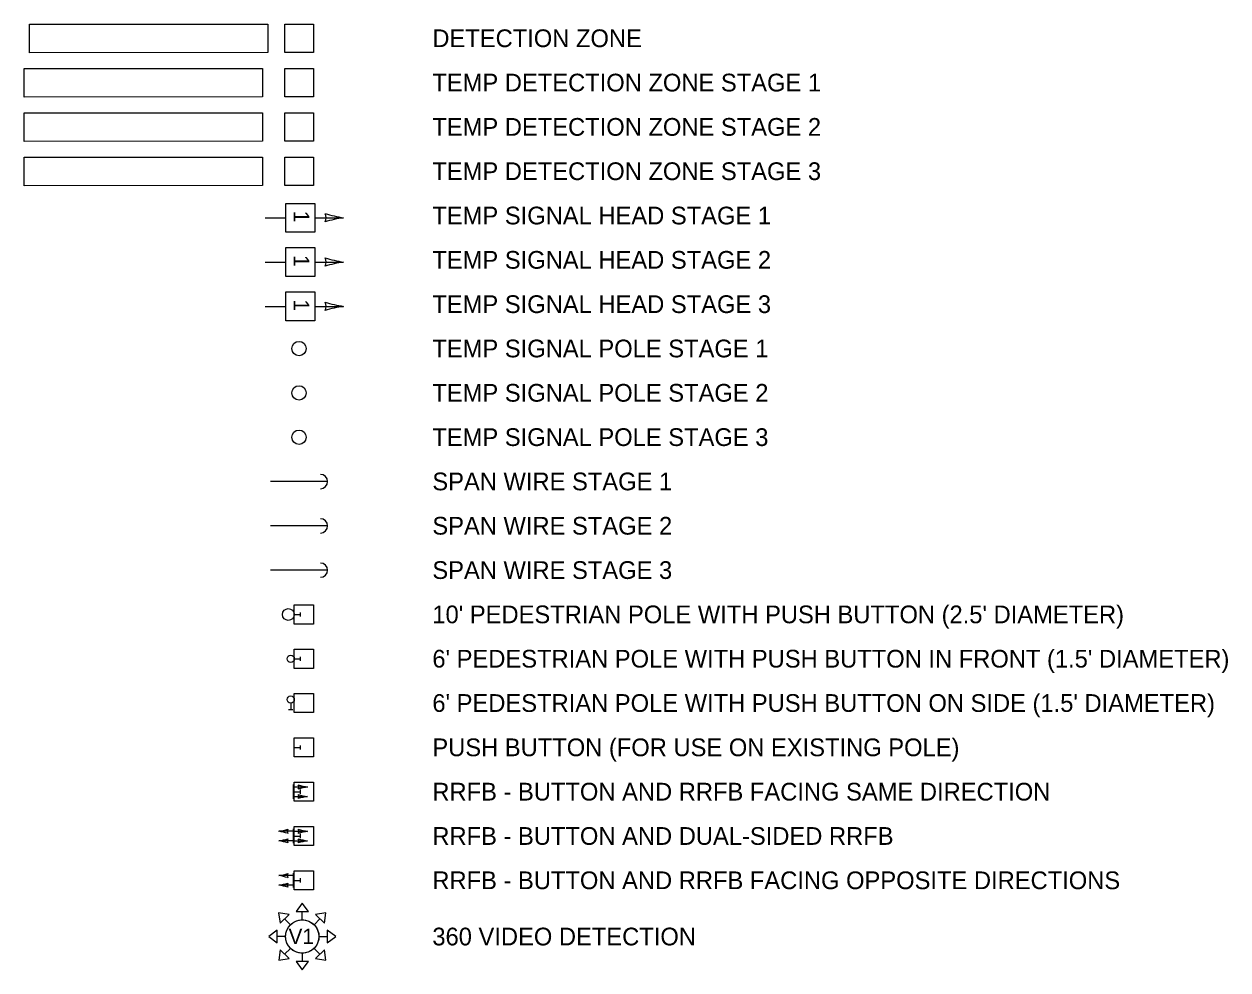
# Model space of a CAD drawing. Extents: x 993729 to 994927, y 1984823 to 1986420.
# Drawn here: x 994024.2 to 994276.7, y 1986017.7 to 1986216.2 of the extents above; entities that cross this region are included whole.
import ezdxf

# ---------------------------------------------------------------- set-up
doc = ezdxf.new("R2010")
doc.units = 0
for name, color, linetype in [('EX_BREAKLINE_PT_SYM', 7, 'Continuous'), ('EX_DROP_INLET_ANNOT', 7, 'Continuous'), ('EX_FIBER_OPTIC_CABLE', 7, 'Continuous'), ('EX_GAS_UTILITIES', 7, 'Continuous'), ('EX_LANDSCAPING', 7, 'Continuous'), ('EX_MANHOLE_ANNOT', 7, 'Continuous'), ('EX_MSC_PT_SYM', 7, 'Continuous'), ('EX_SECONDARY_CTL_ANNOT', 7, 'Continuous'), ('EX_SIGN', 7, 'Continuous'), ('EX_SIGN_ANNOT', 7, 'Continuous'), ('EX_STORM_SEWER_ANNOT', 7, 'Continuous'), ('EX_SURVEY_ANNOT', 7, 'Continuous'), ('EX_TELEPHONE_UTILITIES_ANNOT', 7, 'Continuous'), ('EX_UNDERGROUND_CABLE_ANNOT', 7, 'Continuous'), ('EX_UTILITY_MARKER', 7, 'Continuous')]:
    doc.layers.add(name, color=color, linetype=linetype)

msp = doc.modelspace()

# ---------------------------------------------------------------- linework, layer by layer
at = {"layer": 'EX_BREAKLINE_PT_SYM'}
for p, q in [((994082.59, 1986031.69), (994081.28, 1986029.93)), ((994083.9, 1986029.93), (994082.59, 1986031.69)), ((994079.81, 1986029.32), (994077.63, 1986029.63)), ((994077.63, 1986029.63), (994077.95, 1986027.46)), ((994077.95, 1986027.46), (994079.81, 1986029.32)), ((994081.28, 1986029.93), (994083.9, 1986029.93)), ((994082.59, 1986028.18), (994082.59, 1986029.93)), ((994087.55, 1986029.64), (994085.37, 1986029.32)), ((994085.37, 1986029.32), (994087.23, 1986027.46)), ((994087.23, 1986027.46), (994087.55, 1986029.64)), ((994080.12, 1986027.15), (994078.88, 1986028.39)), ((994085.07, 1986027.15), (994086.3, 1986028.39)), ((994077.34, 1986025.99), (994075.58, 1986024.68)), ((994075.58, 1986024.68), (994077.34, 1986023.37)), ((994077.34, 1986023.37), (994077.34, 1986025.99)), ((994079.09, 1986024.68), (994077.34, 1986024.68)), ((994086.09, 1986024.68), (994087.84, 1986024.68)), ((994087.84, 1986025.99), (994087.84, 1986023.37)), ((994089.6, 1986024.68), (994087.84, 1986025.99)), ((994087.84, 1986023.37), (994089.6, 1986024.68)), ((994077.95, 1986021.89), (994077.64, 1986019.72)), ((994079.81, 1986020.04), (994077.95, 1986021.89)), ((994080.12, 1986022.2), (994078.88, 1986020.97)), ((994085.07, 1986022.2), (994086.3, 1986020.97)), ((994087.23, 1986021.9), (994085.38, 1986020.04)), ((994087.55, 1986019.72), (994087.23, 1986021.9)), ((994077.64, 1986019.72), (994079.81, 1986020.04)), ((994083.9, 1986019.43), (994081.28, 1986019.43)), ((994081.28, 1986019.43), (994082.59, 1986017.67)), ((994082.59, 1986021.18), (994082.59, 1986019.43)), ((994082.59, 1986017.67), (994083.9, 1986019.43)), ((994085.38, 1986020.04), (994087.55, 1986019.72))]:
    msp.add_line(p, q, dxfattribs=at)
msp.add_lwpolyline([(994079.91, 1986026.93), (994080.11, 1986027.15), (994080.34, 1986027.36), (994080.58, 1986027.54), (994080.84, 1986027.71), (994081.11, 1986027.85), (994081.39, 1986027.97), (994081.68, 1986028.06), (994081.98, 1986028.12), (994082.28, 1986028.16), (994082.59, 1986028.18), (994082.89, 1986028.17), (994083.19, 1986028.13), (994083.49, 1986028.06), (994083.78, 1986027.97), (994084.07, 1986027.85), (994084.34, 1986027.71), (994084.59, 1986027.55), (994084.84, 1986027.36), (994085.07, 1986027.15), (994085.27, 1986026.93), (994085.46, 1986026.69), (994085.62, 1986026.43), (994085.76, 1986026.16), (994085.88, 1986025.88), (994085.97, 1986025.59), (994086.04, 1986025.29), (994086.08, 1986024.98), (994086.09, 1986024.68), (994086.08, 1986024.37), (994086.04, 1986024.07), (994085.97, 1986023.77), (994085.88, 1986023.48), (994085.76, 1986023.2), (994085.62, 1986022.93), (994085.46, 1986022.67), (994085.27, 1986022.43), (994085.07, 1986022.2), (994084.84, 1986022), (994084.84, 1986022), (994084.6, 1986021.81), (994084.34, 1986021.65), (994084.07, 1986021.51), (994083.79, 1986021.39), (994083.5, 1986021.3), (994083.2, 1986021.23), (994082.9, 1986021.19), (994082.59, 1986021.18), (994082.29, 1986021.19), (994081.99, 1986021.23), (994081.69, 1986021.3), (994081.4, 1986021.39), (994081.11, 1986021.51), (994080.84, 1986021.65), (994080.59, 1986021.81), (994080.34, 1986022), (994080.12, 1986022.2), (994079.91, 1986022.43), (994079.73, 1986022.67), (994079.56, 1986022.93), (994079.42, 1986023.2), (994079.3, 1986023.48), (994079.21, 1986023.77), (994079.15, 1986024.07), (994079.11, 1986024.37), (994079.09, 1986024.68), (994079.11, 1986024.98), (994079.14, 1986025.28), (994079.21, 1986025.58), (994079.3, 1986025.87), (994079.42, 1986026.16), (994079.56, 1986026.43), (994079.72, 1986026.68)], close=True, dxfattribs=at)
msp.add_circle((994082.59, 1986024.68), 3.5, dxfattribs=at)
at = {"layer": 'EX_DROP_INLET_ANNOT'}
for p, q in [((994074.8, 1986166.19), (994079.14, 1986166.19)), ((994085.21, 1986166.21), (994091.25, 1986166.22))]:
    msp.add_line(p, q, dxfattribs=at)
msp.add_lwpolyline([(994079.15, 1986163.17), (994079.14, 1986169.24), (994085.21, 1986169.24), (994085.21, 1986163.17)], close=True, dxfattribs=at)
for centre, radius, start, end in [((994085.98, 1986166.21), 1.63, 328.1778, 31.8725), ((994095.65, 1986195.36), 29.47, 253.6787, 261.4168), ((994095.67, 1986137.08), 29.47, 98.6335, 106.3716)]:
    msp.add_arc(centre, radius, start, end, dxfattribs=at)
at = {"layer": 'EX_FIBER_OPTIC_CABLE'}
msp.add_line((994087.91, 1986120.17), (994075.91, 1986120.16), dxfattribs=at)
msp.add_arc((994086.41, 1986120.16), 1.5, 270.0252, 90.0252, dxfattribs=at)
at = {"layer": 'EX_GAS_UTILITIES'}
for points in [[(994080.91, 1986094.26), (994084.91, 1986094.26), (994084.91, 1986090.26), (994080.91, 1986090.26)], [(994080.91, 1986084.96), (994084.91, 1986084.96), (994084.91, 1986080.96), (994080.91, 1986080.96)], [(994080.91, 1986075.66), (994084.91, 1986075.66), (994084.91, 1986071.66), (994080.91, 1986071.66)], [(994080.91, 1986066.36), (994084.91, 1986066.36), (994084.91, 1986062.36), (994080.91, 1986062.36)], [(994080.91, 1986057.06), (994084.91, 1986057.06), (994084.91, 1986053.06), (994080.91, 1986053.06)], [(994080.91, 1986047.76), (994084.91, 1986047.76), (994084.91, 1986043.76), (994080.91, 1986043.76)], [(994080.91, 1986038.46), (994084.91, 1986038.46), (994084.91, 1986034.46), (994080.91, 1986034.46)]]:
    msp.add_lwpolyline(points, close=True, dxfattribs=at)
at = {"layer": 'EX_LANDSCAPING'}
for p, q in [((994080.91, 1986092.26), (994082.23, 1986092.26)), ((994082.23, 1986091.82), (994082.23, 1986092.7)), ((994080.91, 1986082.96), (994082.23, 1986082.96)), ((994082.23, 1986082.52), (994082.23, 1986083.4)), ((994079.72, 1986072.34), (994080.6, 1986072.34)), ((994080.16, 1986073.66), (994080.16, 1986072.34)), ((994082.23, 1986063.92), (994082.23, 1986064.8)), ((994080.91, 1986064.36), (994082.23, 1986064.36)), ((994080.91, 1986055.06), (994082.23, 1986055.06)), ((994082.23, 1986054.62), (994082.23, 1986055.5)), ((994080.91, 1986045.76), (994082.23, 1986045.76)), ((994082.23, 1986045.32), (994082.23, 1986046.2)), ((994082.23, 1986036.02), (994082.23, 1986036.9)), ((994080.91, 1986036.46), (994082.23, 1986036.46))]:
    msp.add_line(p, q, dxfattribs=at)
at = {"layer": 'EX_MANHOLE_ANNOT'}
msp.add_line((994087.91, 1986101.57), (994075.91, 1986101.56), dxfattribs=at)
msp.add_circle((994081.9, 1986129.46), 1.5, dxfattribs=at)
msp.add_arc((994086.41, 1986101.56), 1.5, 270.0252, 90.0252, dxfattribs=at)
at = {"layer": 'EX_MSC_PT_SYM'}
for p, q in [((994080.66, 1986056.56), (994080.66, 1986053.56)), ((994080.66, 1986056.06), (994083.68, 1986056.06)), ((994080.66, 1986055.18), (994080.66, 1986054.93)), ((994080.66, 1986055.18), (994080.91, 1986055.18)), ((994080.91, 1986054.93), (994080.66, 1986054.93)), ((994080.91, 1986054.93), (994080.91, 1986055.18)), ((994080.66, 1986054.06), (994083.68, 1986054.06)), ((994080.66, 1986047.26), (994080.66, 1986044.26)), ((994080.66, 1986046.76), (994077.64, 1986046.76)), ((994080.66, 1986044.76), (994077.64, 1986044.76)), ((994080.66, 1986046.76), (994083.68, 1986046.76)), ((994080.66, 1986045.88), (994080.66, 1986045.63)), ((994080.66, 1986045.88), (994080.91, 1986045.88)), ((994080.91, 1986045.63), (994080.66, 1986045.63)), ((994080.66, 1986044.76), (994083.68, 1986044.76)), ((994080.91, 1986045.63), (994080.91, 1986045.88)), ((994080.66, 1986037.46), (994077.64, 1986037.46)), ((994080.66, 1986037.96), (994080.66, 1986034.96)), ((994080.66, 1986035.46), (994077.64, 1986035.46)), ((994080.66, 1986036.58), (994080.66, 1986036.33)), ((994080.66, 1986036.58), (994080.91, 1986036.58)), ((994080.91, 1986036.33), (994080.66, 1986036.33)), ((994080.91, 1986036.33), (994080.91, 1986036.58))]:
    msp.add_line(p, q, dxfattribs=at)
for centre, radius in [((994081.9, 1986148.06), 1.5), ((994079.66, 1986092.26), 1.25), ((994080.16, 1986082.96), 0.75), ((994080.16, 1986074.41), 0.75)]:
    msp.add_circle(centre, radius, dxfattribs=at)
for centre, radius, start, end in [((994081.05, 1986056.06), 0.814, 328.1778, 31.8725), ((994085.88, 1986070.63), 14.74, 253.6787, 261.4168), ((994085.89, 1986041.49), 14.74, 98.6335, 106.3716), ((994081.05, 1986054.06), 0.814, 328.1778, 31.8725), ((994085.88, 1986068.63), 14.74, 253.6787, 261.4168), ((994085.89, 1986039.49), 14.74, 98.6335, 106.3716), ((994075.43, 1986061.33), 14.74, 278.6335, 286.3716), ((994080.27, 1986046.76), 0.814, 148.1778, 211.8725), ((994081.05, 1986046.76), 0.814, 328.1778, 31.8725), ((994085.88, 1986061.33), 14.74, 253.6787, 261.4168), ((994075.44, 1986032.19), 14.74, 73.6787, 81.4168), ((994075.43, 1986059.33), 14.74, 278.6335, 286.3716), ((994075.44, 1986030.19), 14.74, 73.6787, 81.4168), ((994080.27, 1986044.76), 0.814, 148.1778, 211.8725), ((994085.89, 1986032.19), 14.74, 98.6335, 106.3716), ((994081.05, 1986044.76), 0.814, 328.1778, 31.8725), ((994085.88, 1986059.33), 14.74, 253.6787, 261.4168), ((994085.89, 1986030.19), 14.74, 98.6335, 106.3716), ((994075.43, 1986052.03), 14.74, 278.6335, 286.3716), ((994075.44, 1986022.89), 14.74, 73.6787, 81.4168), ((994080.27, 1986037.46), 0.814, 148.1778, 211.8725), ((994075.43, 1986050.03), 14.74, 278.6335, 286.3716), ((994075.44, 1986020.89), 14.74, 73.6787, 81.4168), ((994080.27, 1986035.46), 0.814, 148.1778, 211.8725)]:
    msp.add_arc(centre, radius, start, end, dxfattribs=at)
at = {"layer": 'EX_SECONDARY_CTL_ANNOT'}
for p, q in [((994024.24, 1986206.83), (994074.24, 1986206.86)), ((994024.24, 1986200.83), (994024.24, 1986206.83)), ((994074.24, 1986206.86), (994074.24, 1986200.86)), ((994074.24, 1986200.86), (994024.24, 1986200.83))]:
    msp.add_line(p, q, dxfattribs=at)
msp.add_lwpolyline([(994084.91, 1986200.86), (994078.91, 1986200.86), (994078.91, 1986206.86), (994084.91, 1986206.86)], close=True, dxfattribs=at)
at = {"layer": 'EX_SIGN_ANNOT'}
for p, q in [((994074.8, 1986156.89), (994079.14, 1986156.89)), ((994085.21, 1986156.91), (994091.25, 1986156.92))]:
    msp.add_line(p, q, dxfattribs=at)
msp.add_lwpolyline([(994079.15, 1986153.87), (994079.14, 1986159.94), (994085.21, 1986159.94), (994085.21, 1986153.87)], close=True, dxfattribs=at)
for centre, radius, start, end in [((994085.98, 1986156.91), 1.63, 328.1778, 31.8725), ((994095.65, 1986186.06), 29.47, 253.6787, 261.4168), ((994095.67, 1986127.78), 29.47, 98.6335, 106.3716)]:
    msp.add_arc(centre, radius, start, end, dxfattribs=at)
at = {"layer": 'EX_STORM_SEWER_ANNOT'}
for p, q in [((994074.8, 1986175.49), (994079.14, 1986175.49)), ((994085.21, 1986175.51), (994091.25, 1986175.52))]:
    msp.add_line(p, q, dxfattribs=at)
msp.add_lwpolyline([(994079.15, 1986172.47), (994079.14, 1986178.54), (994085.21, 1986178.54), (994085.21, 1986172.47)], close=True, dxfattribs=at)
for centre, radius, start, end in [((994085.98, 1986175.51), 1.63, 328.1778, 31.8725), ((994095.65, 1986204.66), 29.47, 253.6787, 261.4168), ((994095.67, 1986146.38), 29.47, 98.6335, 106.3716)]:
    msp.add_arc(centre, radius, start, end, dxfattribs=at)
at = {"layer": 'EX_SURVEY_ANNOT'}
for p, q in [((994024.24, 1986188.23), (994074.24, 1986188.26)), ((994024.24, 1986182.23), (994024.24, 1986188.23)), ((994074.24, 1986188.26), (994074.24, 1986182.26)), ((994074.24, 1986182.26), (994024.24, 1986182.23))]:
    msp.add_line(p, q, dxfattribs=at)
msp.add_lwpolyline([(994084.91, 1986182.26), (994078.91, 1986182.26), (994078.91, 1986188.26), (994084.91, 1986188.26)], close=True, dxfattribs=at)
at = {"layer": 'EX_TELEPHONE_UTILITIES_ANNOT'}
msp.add_line((994087.91, 1986110.87), (994075.91, 1986110.86), dxfattribs=at)
msp.add_circle((994081.9, 1986138.76), 1.5, dxfattribs=at)
msp.add_arc((994086.41, 1986110.86), 1.5, 270.0252, 90.0252, dxfattribs=at)
at = {"layer": 'EX_UNDERGROUND_CABLE_ANNOT'}
for p, q in [((994024.24, 1986197.53), (994074.24, 1986197.56)), ((994024.24, 1986191.53), (994024.24, 1986197.53)), ((994074.24, 1986197.56), (994074.24, 1986191.56)), ((994074.24, 1986191.56), (994024.24, 1986191.53))]:
    msp.add_line(p, q, dxfattribs=at)
msp.add_lwpolyline([(994084.91, 1986191.56), (994078.91, 1986191.56), (994078.91, 1986197.56), (994084.91, 1986197.56)], close=True, dxfattribs=at)
at = {"layer": 'EX_UTILITY_MARKER'}
for p, q in [((994025.39, 1986216.13), (994075.39, 1986216.16)), ((994025.39, 1986210.13), (994025.39, 1986216.13)), ((994075.39, 1986216.16), (994075.39, 1986210.16)), ((994075.39, 1986210.16), (994025.39, 1986210.13))]:
    msp.add_line(p, q, dxfattribs=at)
msp.add_lwpolyline([(994084.91, 1986210.16), (994078.91, 1986210.16), (994078.91, 1986216.16), (994084.91, 1986216.16)], close=True, dxfattribs=at)

# ---------------------------------------------------------------- texts
at = {"layer": 'EX_BREAKLINE_PT_SYM'}
msp.add_text('V1', height=3.25, rotation=0.0252, dxfattribs=at).set_placement((994079.71, 1986023.08))
at = {"layer": 'EX_DROP_INLET_ANNOT'}
msp.add_text('1', height=3.25, rotation=270.0252, dxfattribs=at).set_placement((994080.8, 1986167.67))
at = {"layer": 'EX_SIGN'}
for s, p in [('DETECTION ZONE', (994109.87, 1986211.32)), ('TEMP DETECTION ZONE STAGE 1', (994109.87, 1986202.02)), ('TEMP DETECTION ZONE STAGE 2', (994109.87, 1986192.72)), ('TEMP DETECTION ZONE STAGE 3', (994109.87, 1986183.42)), ('TEMP SIGNAL HEAD STAGE 1', (994109.87, 1986174.12)), ('TEMP SIGNAL HEAD STAGE 2', (994109.87, 1986164.82)), ('TEMP SIGNAL HEAD STAGE 3', (994109.87, 1986155.52)), ('TEMP SIGNAL POLE STAGE 1', (994109.87, 1986146.22)), ('TEMP SIGNAL POLE STAGE 2', (994109.87, 1986136.92)), ('TEMP SIGNAL POLE STAGE 3', (994109.87, 1986127.62)), ('SPAN WIRE STAGE 1', (994109.87, 1986118.32)), ('SPAN WIRE STAGE 2', (994109.87, 1986109.02)), ('SPAN WIRE STAGE 3', (994109.87, 1986099.72)), ("10' PEDESTRIAN POLE WITH PUSH BUTTON (2.5' DIAMETER)", (994109.87, 1986090.42)), ("6' PEDESTRIAN POLE WITH PUSH BUTTON IN FRONT (1.5' DIAMETER)", (994109.87, 1986081.12)), ("6' PEDESTRIAN POLE WITH PUSH BUTTON ON SIDE (1.5' DIAMETER)", (994109.87, 1986071.82)), ('PUSH BUTTON (FOR USE ON EXISTING POLE)', (994109.87, 1986062.52)), ('RRFB - BUTTON AND RRFB FACING SAME DIRECTION', (994109.87, 1986053.22)), ('RRFB - BUTTON AND DUAL-SIDED RRFB', (994109.87, 1986043.92)), ('RRFB - BUTTON AND RRFB FACING OPPOSITE DIRECTIONS', (994109.87, 1986034.62)), ('360 VIDEO DETECTION', (994109.87, 1986022.82))]:
    msp.add_text(s, height=3.72, dxfattribs=at).set_placement(p)
at = {"layer": 'EX_SIGN_ANNOT'}
msp.add_text('1', height=3.25, rotation=270.0252, dxfattribs=at).set_placement((994080.8, 1986158.37))
at = {"layer": 'EX_STORM_SEWER_ANNOT'}
msp.add_text('1', height=3.25, rotation=270.0252, dxfattribs=at).set_placement((994080.8, 1986176.97))

doc.saveas('drawing.dxf')
